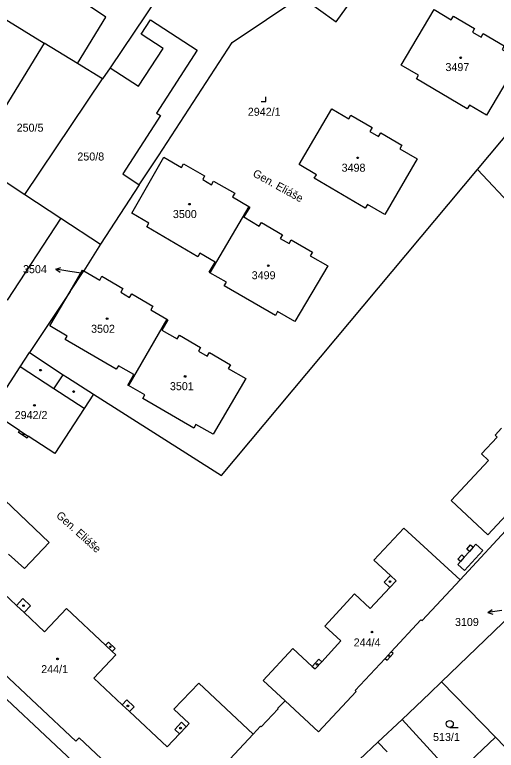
# Model space of a CAD drawing. Extents: x -679220 to -673243, y -1075091 to -1066557.
# Drawn here: x -676070.5 to -675968.3, y -1072022.8 to -1071866.6 of the extents above; entities that cross this region are included whole.
import ezdxf

# ---------------------------------------------------------------- set-up
doc = ezdxf.new("R2010")
doc.units = 0
for name, color, linetype in [('Hranice parcel', 7, 'Continuous'), ('Parcelní čísla', 7, 'Continuous'), ('Pop  PČ popisy', 7, 'Continuous'), ('Vnitřní kresba', 7, 'Continuous'), ('Značky budov', 7, 'Continuous'), ('Značky kultur', 7, 'Continuous')]:
    doc.layers.add(name, color=color, linetype=linetype)

msp = doc.modelspace()

# ---------------------------------------------------------------- linework, layer by layer
at = {"layer": 'Hranice parcel'}
for p, q in [((-676064.23, -1071872.66), (-676075.57, -1071891.12)), ((-676057.21, -1071876.99), (-676064.23, -1071872.66)), ((-676051.88, -1071880.28), (-676057.21, -1071876.99)), ((-676050.28, -1071877.91), (-676051.88, -1071880.28)), ((-676068.34, -1071904.79), (-676051.88, -1071880.28)), ((-675933.77, -1071940.81), (-675972.3, -1071899.52)), ((-676044.09, -1071902.74), (-676052.27, -1071915.35)), ((-676068.34, -1071904.79), (-676060.69, -1071909.82)), ((-676020.81, -1071907.33), (-676029.07, -1071921.43)), ((-676060.69, -1071909.82), (-676052.27, -1071915.35)), ((-676052.27, -1071915.35), (-676055.87, -1071921.01)), ((-676058.77, -1071925.38), (-676055.87, -1071921.01)), ((-676058.77, -1071925.38), (-676067.39, -1071938.4)), ((-676038.21, -1071931.31), (-676046.34, -1071945.38)), ((-675976.01, -1071986.64), (-675960.63, -1071969.95)), ((-675968.52, -1072020.07), (-675979.93, -1072008.33)), ((-675977.27, -1072028.34), (-675968.52, -1072020.07)), ((-675957.19, -1072031.72), (-675968.52, -1072020.07))]:
    msp.add_line(p, q, dxfattribs=at)
for points in [[(-676009.82, -1071862.71), (-676002.3, -1071868.17), (-675993.51, -1071855.91), (-675992.23, -1071856.82), (-675990.89, -1071854.93), (-675992.16, -1071854.02), (-675983.47, -1071841.89), (-675983.1, -1071842.15), (-675981.75, -1071840.27), (-675982.12, -1071840.01), (-675981.75, -1071839.49)], [(-675972.3, -1071899.52), (-675944.27, -1071866), (-675981.75, -1071839.49)], [(-676108.73, -1071845.19), (-676096.94, -1071852.46), (-676087.97, -1071858.01), (-676064.23, -1071872.66)], [(-676057.21, -1071876.99), (-676051.14, -1071867.14), (-676059.16, -1071861.69)], [(-676040.22, -1071862.93), (-676050.28, -1071877.91)], [(-676044.09, -1071902.74), (-676039.99, -1071896.63), (-676024.38, -1071872.53), (-676009.82, -1071862.71)], [(-675974.04, -1071885.88), (-675974.48, -1071886.66), (-675985.28, -1071880.25), (-675984.82, -1071879.48), (-675988.52, -1071877.33), (-675981.52, -1071865.56), (-675977.87, -1071867.73), (-675977.42, -1071866.97), (-675972.94, -1071869.58), (-675973.39, -1071870.35), (-675971.55, -1071871.42), (-675971.1, -1071870.64), (-675966.64, -1071873.24), (-675967.09, -1071874.01), (-675963.43, -1071876.16), (-675970.37, -1071888), (-675974.04, -1071885.88)], [(-676050.28, -1071877.91), (-676044.24, -1071881.83), (-676039.03, -1071873.79), (-676043.65, -1071870.8), (-676041.67, -1071867.73), (-676031.76, -1071874.15), (-676040.42, -1071887.52), (-676039.58, -1071888.06), (-676047.57, -1071900.4), (-676044.09, -1071902.74)], [(-675994.68, -1071890.62), (-675995.14, -1071891.41), (-675993.3, -1071892.49), (-675992.84, -1071891.7), (-675988.36, -1071894.31), (-675988.81, -1071895.09), (-675985.11, -1071897.23), (-675991.96, -1071909.08), (-675995.66, -1071906.94), (-675996.11, -1071907.71), (-676006.93, -1071901.38), (-676006.49, -1071900.61), (-676010.15, -1071898.47), (-676003.25, -1071886.66), (-675999.63, -1071888.78), (-675999.17, -1071888), (-675994.68, -1071890.62)], [(-676083.84, -1071894.72), (-676078.58, -1071898.15), (-676073.59, -1071901.34), (-676068.34, -1071904.79)], [(-676029.07, -1071921.43), (-676029.26, -1071921.32), (-676027.99, -1071919.16), (-676031.22, -1071917.29), (-676031.67, -1071918.05), (-676042.49, -1071911.7), (-676042.04, -1071910.93), (-676045.64, -1071908.79), (-676038.88, -1071896.91), (-676035.12, -1071899.07), (-676034.66, -1071898.29), (-676030.2, -1071900.87), (-676030.62, -1071901.64), (-676028.76, -1071902.73), (-676028.32, -1071901.96), (-676023.83, -1071904.56), (-676024.3, -1071905.34), (-676020.81, -1071907.33)], [(-676053.8, -1071947.23), (-676026.62, -1071964.49), (-675972.3, -1071899.52)], [(-676020.81, -1071907.33), (-676020.64, -1071907.48), (-676021.9, -1071909.59), (-676018.62, -1071911.54), (-676018.17, -1071910.76), (-676013.71, -1071913.35), (-676014.17, -1071914.13), (-676012.26, -1071915.22), (-676011.81, -1071914.45), (-676007.33, -1071917.05), (-676007.78, -1071917.84), (-676004.09, -1071919.93), (-676011.06, -1071931.8), (-676014.73, -1071929.69), (-676015.18, -1071930.48), (-676026.04, -1071924.22), (-676025.59, -1071923.44), (-676029.07, -1071921.43)], [(-676060.69, -1071909.82), (-676072.12, -1071927.28), (-676072.56, -1071926.99), (-676082.57, -1071942.38), (-676082.45, -1071942.45), (-676084.83, -1071946.11), (-676084.95, -1071946.03), (-676094.87, -1071961.29), (-676094.43, -1071961.58), (-676105.42, -1071978.58)], [(-676058.77, -1071925.38), (-676056.14, -1071920.85), (-676055.87, -1071921.01)], [(-676055.87, -1071921.01), (-676052.47, -1071923), (-676052, -1071922.19), (-676047.55, -1071924.79), (-676047.99, -1071925.58), (-676046.13, -1071926.67), (-676045.65, -1071925.89), (-676041.18, -1071928.51), (-676041.64, -1071929.3), (-676038.21, -1071931.31)], [(-676046.34, -1071945.38), (-676046.53, -1071945.27), (-676045.24, -1071943.07), (-676048.51, -1071941.17), (-676048.96, -1071941.94), (-676059.8, -1071935.64), (-676059.35, -1071934.87), (-676063.04, -1071932.72), (-676058.77, -1071925.38)], [(-676038.21, -1071931.31), (-676038.02, -1071931.42), (-676039.28, -1071933.59), (-676036, -1071935.46), (-676035.54, -1071934.68), (-676031.09, -1071937.28), (-676031.54, -1071938.05), (-676029.65, -1071939.15), (-676029.19, -1071938.39), (-676024.72, -1071941), (-676025.18, -1071941.79), (-676021.49, -1071943.9), (-676028.4, -1071955.74), (-676032.06, -1071953.63), (-676032.5, -1071954.4), (-676043.32, -1071948.16), (-676042.87, -1071947.38), (-676046.34, -1071945.38)], [(-676075.57, -1071950.97), (-676069.33, -1071941.38), (-676067.39, -1071938.4)], [(-676067.39, -1071938.4), (-676060.25, -1071943.08), (-676059.33, -1071943.69), (-676053.8, -1071947.23)], [(-676053.8, -1071947.23), (-676055.77, -1071950.27), (-676061.98, -1071959.83), (-676067.63, -1071956.15), (-676067.87, -1071956.53), (-676069.71, -1071955.33), (-676069.47, -1071954.95), (-676075.57, -1071950.97)], [(-675962.14, -1071968.54), (-675970.11, -1071977.08), (-675977.9, -1071969.82), (-675969.96, -1071961.29), (-675971.46, -1071959.9), (-675968.17, -1071956.32), (-675968.58, -1071955.94), (-675967.2, -1071954.42)], [(-676013.15, -1072012.32), (-676017.77, -1072008.03), (-676011.5, -1072001.24), (-676007.36, -1072005.03), (-676005.96, -1072003.5), (-676005.37, -1072004.04), (-676001.29, -1071999.59), (-676004.71, -1071996.45), (-675998.4, -1071989.62), (-675995.05, -1071992.73), (-675990.91, -1071988.27), (-675992.14, -1071987.14), (-675990.8, -1071985.69), (-675994.27, -1071982.47), (-675987.92, -1071975.64), (-675976.01, -1071986.64)], [(-676025.75, -1072065.64), (-676034.25, -1072051.8), (-676039.72, -1072042.53), (-676096.55, -1071989.19), (-676094.44, -1071985.56)], [(-676092.58, -1071986.74), (-676084.09, -1071994.75), (-676083.99, -1071994.64), (-676073.48, -1072004.6), (-676074.16, -1072005.33), (-676057.51, -1072020.9), (-676056.82, -1072020.17), (-676046.21, -1072030.2), (-676046.31, -1072030.3), (-676037.74, -1072038.5)], [(-676013.15, -1072012.32), (-676006.04, -1072018.92), (-675998.05, -1072010.37), (-675998.27, -1072010.16), (-675991.91, -1072003.32), (-675991.51, -1072003.69), (-675990.22, -1072002.3), (-675990.62, -1072001.92), (-675984.3, -1071995.11), (-675984.08, -1071995.31), (-675976.01, -1071986.64)], [(-675964.77, -1071993.39), (-675965.23, -1071993.86), (-675965.1, -1071993.99), (-675979.93, -1072008.33)], [(-675979.93, -1072008.33), (-675982.39, -1072010.71), (-675988.29, -1072016.27)], [(-676037.74, -1072038.5), (-676019.92, -1072019.42), (-676018.32, -1072017.74), (-676018.23, -1072017.83), (-676014.59, -1072014.01), (-676014.67, -1072013.92), (-676013.15, -1072012.32)], [(-675988.29, -1072016.27), (-675993.45, -1072021.14), (-675997.34, -1072024.81), (-676000.8, -1072028.07), (-676009.28, -1072035.69), (-676009.2, -1072035.78), (-676016.47, -1072042.6), (-676017.87, -1072041.11), (-676028.71, -1072050.67)], [(-675977.27, -1072028.34), (-675980.08, -1072025.26), (-675988.29, -1072016.27)]]:
    msp.add_lwpolyline(points, dxfattribs=at)
at = {"layer": 'Pop  PČ popisy'}
for p, q in [((-676061.79, -1071920.68), (-676060.73, -1071920.34)), ((-676058.83, -1071921.15), (-676061.79, -1071920.68)), ((-676061.79, -1071920.68), (-676060.88, -1071921.33)), ((-676056.37, -1071921.55), (-676058.83, -1071921.15)), ((-675970.14, -1071993.6), (-675969.22, -1071992.96)), ((-675967.17, -1071993.18), (-675970.14, -1071993.6)), ((-675970.14, -1071993.6), (-675969.08, -1071993.95))]:
    msp.add_line(p, q, dxfattribs=at)
at = {"layer": 'Vnitřní kresba'}
for p, q in [((-676062.19, -1071946.05), (-676069.33, -1071941.38)), ((-676062.19, -1071946.05), (-676060.25, -1071943.08)), ((-676055.77, -1071950.27), (-676062.19, -1071946.05)), ((-676069.47, -1071954.95), (-676067.63, -1071956.15)), ((-676074.67, -1071967.81), (-676063.2, -1071978.68)), ((-676063.2, -1071978.68), (-676068.43, -1071984.26)), ((-675974.57, -1071980.12), (-675973.76, -1071979.23)), ((-675973.22, -1071979.72), (-675974.02, -1071980.61)), ((-675973.76, -1071979.23), (-675973.22, -1071979.72)), ((-675973.22, -1071979.72), (-675972.63, -1071979.07)), ((-675972.63, -1071979.07), (-675971.18, -1071980.39)), ((-676068.43, -1071984.26), (-676071.8, -1071981.17)), ((-675976.48, -1071982.23), (-675975.65, -1071981.32)), ((-675975.65, -1071981.32), (-675975.11, -1071981.81)), ((-675975.11, -1071981.81), (-675974.02, -1071980.61)), ((-675971.18, -1071980.39), (-675975.07, -1071984.66)), ((-675974.02, -1071980.61), (-675974.57, -1071980.12)), ((-675976.51, -1071983.35), (-675975.94, -1071982.72)), ((-675975.94, -1071982.72), (-675976.48, -1071982.23)), ((-675975.11, -1071981.81), (-675975.94, -1071982.72)), ((-675975.07, -1071984.66), (-675976.51, -1071983.35)), ((-676076.47, -1071986.11), (-676070.11, -1071992.08)), ((-675990.8, -1071985.69), (-675989.57, -1071986.83)), ((-675989.57, -1071986.83), (-675990.91, -1071988.27)), ((-676068.76, -1071990.64), (-676070.11, -1071992.08)), ((-676067.17, -1071992.13), (-676068.76, -1071990.64)), ((-676070.11, -1071992.08), (-676068.53, -1071993.57)), ((-676068.53, -1071993.57), (-676067.17, -1071992.13)), ((-676068.53, -1071993.57), (-676064.19, -1071997.65)), ((-676064.19, -1071997.65), (-676059.49, -1071992.71)), ((-676059.49, -1071992.71), (-676051.21, -1072000.54)), ((-676051.21, -1072000.54), (-676050.59, -1071999.89)), ((-676050.59, -1071999.89), (-676049.19, -1072001.21)), ((-676051.21, -1072000.54), (-676049.81, -1072001.86)), ((-676049.19, -1072001.21), (-676049.81, -1072001.86)), ((-676049.81, -1072001.86), (-676049.04, -1072002.59)), ((-675991.91, -1072003.32), (-675990.62, -1072001.92)), ((-676049.04, -1072002.59), (-676053.71, -1072007.53)), ((-676007.36, -1072005.03), (-676006.77, -1072005.57)), ((-676006.77, -1072005.57), (-676005.37, -1072004.04)), ((-676053.71, -1072007.53), (-676047.69, -1072013.17)), ((-676036.74, -1072014.11), (-676031.46, -1072008.57)), ((-676031.46, -1072008.57), (-676019.92, -1072019.42)), ((-676047.69, -1072013.17), (-676046.74, -1072012.15)), ((-676046.74, -1072012.15), (-676045.18, -1072013.6)), ((-676046.14, -1072014.62), (-676047.69, -1072013.17)), ((-676045.18, -1072013.6), (-676046.14, -1072014.62)), ((-676033.47, -1072017.16), (-676036.74, -1072014.11)), ((-676046.14, -1072014.62), (-676038.12, -1072022.13)), ((-676036.56, -1072018.41), (-676035.12, -1072016.88)), ((-676035.12, -1072016.88), (-676034.1, -1072017.83)), ((-676034.1, -1072017.83), (-676033.47, -1072017.16)), ((-676035.54, -1072019.37), (-676036.56, -1072018.41)), ((-676035.54, -1072019.37), (-676034.1, -1072017.83)), ((-676038.12, -1072022.13), (-676035.54, -1072019.37)), ((-675993.45, -1072021.14), (-675991.45, -1072023.19))]:
    msp.add_line(p, q, dxfattribs=at)
at = {"layer": 'Značky budov'}
for centre, radius in [((-675975.87, -1071875.78), 0.175), ((-675997.75, -1071897.03), 0.175), ((-676033.43, -1071906.87), 0.175), ((-676016.69, -1071919.94), 0.175), ((-676056.08, -1071921.07), 0.117), ((-676050.89, -1071931.17), 0.175), ((-676065.02, -1071942.12), 0.175), ((-676034.34, -1071943.46), 0.175), ((-676058.01, -1071946.66), 0.175), ((-676066.32, -1071949.58), 0.175), ((-676068.68, -1071955.74), 0.117), ((-675990.86, -1071987), 0.175), ((-676068.64, -1071992.11), 0.175), ((-675994.7, -1071997.73), 0.175), ((-676050.21, -1072000.87), 0.175), ((-676061.42, -1072003.42), 0.175), ((-675991.07, -1072002.8), 0.117), ((-676006.36, -1072004.56), 0.175), ((-676046.49, -1072013.4), 0.175), ((-676035.32, -1072018.13), 0.175)]:
    msp.add_circle(centre, radius, dxfattribs=at)
at = {"layer": 'Značky kultur'}
for p, q in [((-676017.19, -1071885.06), (-676017.19, -1071884.06)), ((-676018.19, -1071885.06), (-676017.19, -1071885.06)), ((-675978.19, -1072017.99), (-675976.44, -1072017.99))]:
    msp.add_line(p, q, dxfattribs=at)
msp.add_circle((-675978.19, -1072017.24), 0.75, dxfattribs=at)

# ---------------------------------------------------------------- texts
at = {"layer": 'Parcelní čísla'}
for s, p in [('3497', (-675979.11, -1071878.61)), ('2942/1', (-676021.04, -1071888.1)), ('250/5', (-676070.09, -1071891.48)), ('250/8', (-676057.21, -1071897.6)), ('3498', (-676001.14, -1071899.98)), ('3500', (-676036.94, -1071909.82)), ('3504', (-676068.74, -1071921.52)), ('3499', (-676020.22, -1071922.81)), ('3502', (-676054.3, -1071934.18)), ('3501', (-676037.57, -1071946.37)), ('2942/2', (-676070.51, -1071952.5)), ('3109', (-675977.09, -1071996.44)), ('244/4', (-675998.58, -1072000.79)), ('244/1', (-676064.88, -1072006.46)), ('513/1', (-675981.74, -1072020.86))]:
    msp.add_text(s, height=1.7, dxfattribs=at).set_placement(p)
at = {"layer": 'Pop  PČ popisy'}
for rotation, p in [(331, (-676020.15, -1071900.84)), (318, (-676061.85, -1071973.18))]:
    msp.add_text('Gen. Eliáše', height=1.7, rotation=rotation, dxfattribs=at).set_placement(p)

doc.saveas('drawing.dxf')
